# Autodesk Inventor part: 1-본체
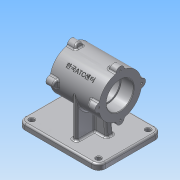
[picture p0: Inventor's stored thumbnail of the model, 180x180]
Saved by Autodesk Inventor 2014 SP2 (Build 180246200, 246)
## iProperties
Created: 2015-12
Part Number: 1-본체
Material: 알루미늄 6061
Document SubType Name: Modeling
Designer: Administrator
Density: 2.71 g/cm^3
Appearance: 알루미늄 - 평지
Mass: 1165.51 g
Surface Area: 815.985 cm^2
Volume: 430.078 cm^3
Author: Administrator
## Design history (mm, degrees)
sketch "스케치1"
  geometry: L1 (-80, 55)-(60, 55); L2 (60, 55)-(60, -55); L3 (60, -55)-(-80, -55); L4 (-80, -55)-(-80, 55); 2 further points
  constraints: 8 end point, 2 parallel, 1 horizontal, 1 horizontal alignment, 1 midpoint, 1 perpendicular
  dimensions: "d0" = 140 distance of L1.start L1.end; "d1" = 110 distance of L1.end L2.end; "d2" = 80 distance from line of point (0, 0) L4
extrude "돌출1" new body sketch "스케치1" distance "d3" = 10; taper "d4" = 0 deg
fillet "모깎기1" dims "d5" = 12
fillet "모깎기2" dims "d6" = 3
sketch "스케치2"
  geometry: A1 r 9 centre (48, -43) between (48, -52) and (57, -43) reference; A2 r 9 centre (48, 43) between (57, 43) and (48, 52) reference; A3 r 9 centre (-68, 43) between (-68, 52) and (-77, 43) reference; A4 r 9 centre (-68, -43) between (-77, -43) and (-68, -52) reference; 1 further point
hole "구멍1" sketch "스케치2" at (-68, -43), (48, -43), (48, 43), (-68, 43) diameter "d7" = 8; stored, may be unused: countersink angle "d11" = 90 deg, drill point angle "d13" = 118 deg; dims "d8" = 6, "d9" = 4, "d10" = 2, "d12" = 8
node "작업 평면1"
sketch "스케치3"
  geometry: L1 (0, 37)-(0, -37); 2 further points
  constraints: 2 end point, 1 coincident, 1 midpoint, 1 vertical
  dimensions: "d15" = 74 distance of L1.start L1.end
feature "리브1" sketch "스케치3" dims "d16" = 8, "d17" = 1, "d18" = 0, "d19" = 0, "d20" = 1, "d21" = 1
sketch "스케치4"
  geometry: L1 (-43, 0)-(43, 0) reference; C1 r 37 at (0, 80); 1 further point
  constraints: 1 centre point
  dimensions: "d22" = 80 distance from line of L1 C1.centre; "d23" = 74 diameter of C1
extrude "돌출2" join sketch "스케치4" stored distance "d24" = 85; taper "d25" = 0 deg
sketch "스케치5"
  geometry: L1 (80, 7)-(80, 0) reference; L2 (80, 0)-(-60, 0) reference; L3 (-60, 0)-(-60, 7) reference; L4 (-57, 10)-(-4, 10) reference; L5 (-4, 10)-(-4, 43) reference; L6 (-4, 43)-(-42.5, 43) reference; L7 (-42.5, 43)-(-42.5, 117) reference; L8 (-42.5, 117)-(42.5, 117) reference; L9 (42.5, 117)-(42.5, 43) reference; L10 (42.5, 43)-(4, 43) reference; L11 (4, 43)-(4, 10) reference; L12 (4, 10)-(77, 10) reference; L13 (-25, 10)-(-21.667, 37.148); L14 (0, 0)-(0, 47.319); A1 r 3 centre (77, 7) between (80, 7) and (77, 10) reference; A2 r 3 centre (-57, 7) between (-57, 10) and (-60, 7) reference
  constraints: 4 end point, 1 parallel, 1 point on line
  dimensions: "d26" = 25 horizontal distance of L14.start L13.start; "d27" = 97 deg angle of L13 L4; "d76" = 50 diameter of L13.start L14 (derived)
feature "리브2" sketch "스케치5" dims "d28" = 1, "d29" = 12, "d30" = 0, "d31" = 0, "d32" = 1, "d33" = 1
sketch "스케치6"
  geometry: C1 r 7 at (-37, 0); 2 further points
  constraints: 1 centre point, 1 horizontal alignment, 1 other
  dimensions: "d34" = 14 diameter of C1
extrude "돌출3" join sketch "스케치6" distance "d35" = 15; taper "d36" = 0 deg
sketch "스케치7"
  geometry: L1 (80, 0)-(-60, 0) reference; L2 (-60, 0)-(-60, 7) reference; L3 (-57, 10)-(-25, 10) reference; L4 (-25, 10)-(-20.948, 43) reference; L5 (-20.948, 43)-(-42.5, 43) reference; L6 (-42.5, 43)-(-42.5, 124) reference; L7 (-42.5, 124)-(-27.5, 124) reference; L8 (-27.5, 124)-(-27.5, 117) reference; L9 (-27.5, 117)-(42.5, 117) reference; L10 (42.5, 117)-(42.5, 43) reference; L11 (42.5, 43)-(20.948, 43) reference; L12 (20.948, 43)-(25, 10) reference; L13 (25, 10)-(77, 10) reference; L14 (80, 7)-(80, 0) reference; L15 (80, 0)-(-60, 0) reference; L16 (-60, 0)-(-60, 7) reference; L17 (-57, 10)-(-25, 10) reference; L18 (-25, 10)-(-20.948, 43) reference; L19 (-20.948, 43)-(-42.5, 43) reference; L20 (-42.5, 43)-(-42.5, 124) reference; L21 (-42.5, 124)-(-27.5, 124) reference; L22 (-27.5, 124)-(-27.5, 117) reference; L23 (-27.5, 117)-(42.5, 117) reference; L24 (42.5, 117)-(42.5, 43) reference; L25 (42.5, 43)-(20.948, 43) reference; L26 (20.948, 43)-(25, 10) reference; L27 (25, 10)-(77, 10) reference; L28 (80, 7)-(80, 0) reference; L29 (-27.5, 117)-(-30.048, 124); L30 (42.5, 80)-(-42.5, 80); A1 r 3 centre (-57, 7) between (-57, 10) and (-60, 7) reference; A2 r 3 centre (77, 7) between (80, 7) and (77, 10) reference; A3 r 3 centre (-57, 7) between (-57, 10) and (-60, 7) reference; A4 r 3 centre (77, 7) between (80, 7) and (77, 10) reference; 1 further point
  constraints: 4 end point, 2 point on line, 1 midpoint, 1 perpendicular
  dimensions: "d37" = 110 deg angle of L9 L29
revolve "회전1" sketch "스케치7" stored, may be unused: angle "d38" = 90 deg
sketch "스케치8"
  geometry: A1 r 7 centre (-117, 0) between (-116.338, 6.969) and (-116.338, -6.969) reference; 3 further points
hole "구멍2" sketch "스케치8" at (-117, 0) diameter "d41" = 3.242; stored, may be unused: countersink angle "d45" = 90 deg, drill point angle "d47" = 118 deg; dims "d42" = 9, "d43" = 4, "d44" = 2, "d46" = 11
fillet "모깎기8" dims "d74" = 3
fillet "모깎기9" dims "d75" = 3
fillet "모깎기5" dims "d51" = 3
fillet "모깎기6" dims "d52" = 3
sketch "스케치9"
  geometry: A1 r 37 centre (-80, 0) between (-44.138, 9.104) and (-70.896, 35.863) reference; 3 further points
hole "구멍3" sketch "스케치9" at (-80, 0) diameter "d53" = 42; stored, may be unused: countersink angle "d57" = 90 deg, drill point angle "d59" = 118 deg; dims "d54" = 9, "d55" = 47, "d56" = 22, "d58" = 11
chamfer "모따기1" distance "d60" = 1; stored, may be unused: second distance "d61" = 2, angle "d62" = 45 deg
fillet "모깎기7" dims "d63" = 0.3
sketch "스케치10"
  geometry: L1 (55, 0)-(-55, 0) reference; L2 (-55, 0)-(-55, 7) reference; L3 (-52, 10)-(-40, 10) reference; L4 (-37, 13)-(-37, 80) reference; L5 (37, 80)-(37, 13) reference; L6 (40, 10)-(52, 10) reference; L7 (55, 7)-(55, 0) reference; L8 (0, 80)-(-37, 80); L9 (0, 80)-(-30.979, 110.979); C1 r 21 at (0, 80) reference; A1 r 3 centre (-52, 7) between (-52, 10) and (-55, 7) reference; A2 r 3 centre (-40, 13) between (-40, 10) and (-37, 13) reference; A3 r 37 centre (0, 80) between (37, 80) and (-37, 80) reference; A4 r 3 centre (40, 13) between (37, 13) and (40, 10) reference; A5 r 3 centre (52, 7) between (55, 7) and (52, 10) reference; 1 further point
  constraints: 4 end point, 1 point on circle
  dimensions: "d64" = 45 deg angle of L8 L9
  node "절단 모서리 투영4"
node "작업 평면2"
sketch "스케치11"
  geometry: 7 further points; 1 other entity
  constraints: 1 coincident, 1 vertical alignment, 1 other
  dimensions: "d65" = 42.5 dimension on point (0, 0) (derived)
feature "엠보싱1" sketch "스케치11" dims "d0" = 140, "d1" = 110, "d2" = 80, "d66" = 0.5, "d67" = 0
chamfer "모따기2" distance "d68" = 1; stored, may be unused: second distance "d69" = 2, angle "d70" = 45 deg
node "솔리드1"
mirror "대칭1"
pattern_circular "원형 패턴2" dims "d72" = 360 deg
mirror "대칭4"
mirror "대칭3"
node "절단 모서리 투영1"
node "절단 모서리 투영2"
node "절단 모서리 투영3"
